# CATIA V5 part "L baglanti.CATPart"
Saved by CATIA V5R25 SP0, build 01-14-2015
Part number: giris
Bounding box of the stored display mesh (mm): x 0 to 10, y -12.486 to 307.486, z -12.5 to 12.5
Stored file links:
  C:\Users\Aidata\Downloads\L baglanti.CATPart
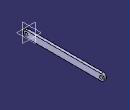
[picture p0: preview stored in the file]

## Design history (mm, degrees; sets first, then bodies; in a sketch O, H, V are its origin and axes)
Body1 (main body)
  Sketch1 on yz-plane, origin (0, 0, 0), H (0, 1, 0), V (0, 0, 1)
    construction line L1 (0, 0) -> (295, 0)
    line L2 (0, 12.5) -> (295, 12.5)
    line L3 (295, -12.5) -> (0, -12.5)
    arc A1 centre (295, 0) radius 12.5 from (295, 12.5) to (295, -12.5) cw
    arc A2 centre (0, 0) radius 12.5 from (0, -12.5) to (0, 12.5) cw
    circle A3 centre (0, 0) radius 6
    circle A4 centre (295, 0) radius 6
    distance L3 L2 = 25
    radius A3 = 6
    radius A4 = 6
    distance A1 A2 = 320
    horizontal: L1 H
    tangency: A1 L2, A2 L2, A1 L3, A2 L3
  Pad1: profile Sketch1, direction (1, 0, 0), length 10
